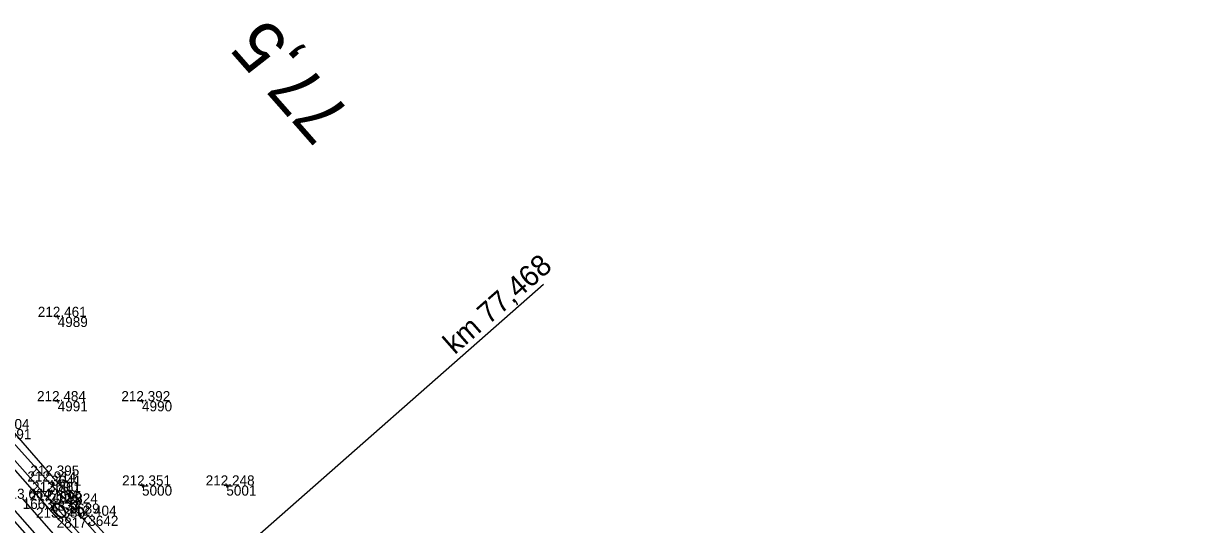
# Model space of a CAD drawing. Extents: x -556590 to -554855, y -1137918 to -1135717.
# Drawn here: x -555624.1 to -555484.8, y -1136484.6 to -1136425.2 of the extents above; entities that cross this region are included whole.
import ezdxf

# ---------------------------------------------------------------- set-up
doc = ezdxf.new("R2010")
doc.units = 0
for name, color, linetype in [('Vrstva 1', 7, 'Continuous'), ('Vrstva 4', 7, 'Continuous'), ('Vrstva 48', 7, 'Continuous'), ('Vrstva 49', 7, 'Continuous'), ('Vrstva 60', 7, 'Continuous'), ('Vrstva 61', 7, 'Continuous'), ('Vrstva 7', 7, 'Continuous'), ('Vrstva 9', 7, 'Continuous')]:
    doc.layers.add(name, color=color, linetype=linetype)

msp = doc.modelspace()

# ---------------------------------------------------------------- linework, layer by layer
at = {"layer": 'Vrstva 1'}
msp.add_lwpolyline([(-555484.83, -1136640), (-555491.53, -1136632.38), (-555498.41, -1136624.55), (-555504.95, -1136617.11), (-555511.61, -1136609.53), (-555518.45, -1136601.75), (-555525.81, -1136593.38), (-555532.45, -1136585.84), (-555538.8, -1136578.61), (-555545.38, -1136571.15), (-555549.37, -1136566.6), (-555556.02, -1136559.04), (-555563.24, -1136550.83), (-555569.21, -1136544.04), (-555575.76, -1136536.6), (-555582.67, -1136528.74), (-555589.18, -1136521.33), (-555595.93, -1136513.66), (-555603.17, -1136505.43), (-555610, -1136497.67), (-555617.05, -1136489.66), (-555624.15, -1136481.58)], dxfattribs=at)
at = {"layer": 'Vrstva 4'}
for points in [[(-555629.91, -1136471.62), (-555620.89, -1136481.78), (-555617.27, -1136485.88)], [(-555633.98, -1136472.93), (-555622.46, -1136485.97), (-555610.79, -1136499.26), (-555598.98, -1136512.7), (-555590.54, -1136522.31), (-555579.05, -1136535.31), (-555569.81, -1136545.79), (-555557.36, -1136559.91), (-555552.62, -1136565.36), (-555551.75, -1136566.43), (-555551.55, -1136566.96), (-555551.52, -1136567.33), (-555551.58, -1136567.56), (-555554.52, -1136564.03), (-555567.11, -1136549.89), (-555580.38, -1136534.94), (-555595.88, -1136517.38), (-555608.09, -1136503.55), (-555622.43, -1136487.28), (-555632.95, -1136475.38)], [(-555527.95, -1136588.27), (-555529.84, -1136586.47), (-555535.2, -1136580.28), (-555544.63, -1136569.62), (-555554.91, -1136557.94), (-555561.61, -1136550.38), (-555568.59, -1136542.49), (-555575.12, -1136534.99), (-555586.39, -1136522.08), (-555596.44, -1136510.59), (-555607.81, -1136497.74), (-555613.59, -1136490.92), (-555614.19, -1136490.14), (-555614.5, -1136489.88), (-555614.86, -1136489.81), (-555615.23, -1136489.54), (-555615.64, -1136488.97), (-555615.94, -1136488.43), (-555617.22, -1136486.81), (-555618.03, -1136485.9), (-555620.12, -1136483.81), (-555629.06, -1136473.63)]]:
    msp.add_lwpolyline(points, dxfattribs=at)
at = {"layer": 'Vrstva 48'}
for p, q in [((-555617.9, -1136482.92), (-555617.4, -1136482.48)), ((-555617.41, -1136483.48), (-555617.15, -1136483.25)), ((-555616.91, -1136484.04), (-555616.38, -1136483.58)), ((-555616.41, -1136484.6), (-555616.15, -1136484.37))]:
    msp.add_line(p, q, dxfattribs=at)
at = {"layer": 'Vrstva 49'}
for p, q in [((-555619.75, -1136459.95), (-555620.25, -1136460.05)), ((-555620.05, -1136459.75), (-555619.95, -1136460.25)), ((-555619.75, -1136469.95), (-555620.25, -1136470.05)), ((-555620.05, -1136469.75), (-555619.95, -1136470.25)), ((-555609.75, -1136469.95), (-555610.25, -1136470.05)), ((-555610.05, -1136469.75), (-555609.95, -1136470.25)), ((-555620.72, -1136480.53), (-555620.63, -1136481.02)), ((-555609.75, -1136479.95), (-555610.25, -1136480.05)), ((-555610.05, -1136479.75), (-555609.95, -1136480.25)), ((-555599.75, -1136479.95), (-555600.25, -1136480.05)), ((-555600.05, -1136479.75), (-555599.95, -1136480.25)), ((-555620.43, -1136480.73), (-555620.92, -1136480.82))]:
    msp.add_line(p, q, dxfattribs=at)
for points in [[(-555628.03, -1136470.49), (-555620.78, -1136478.83), (-555616.37, -1136483.59), (-555611.35, -1136489.14)], [(-555614.37, -1136486.92), (-555618.59, -1136482.14), (-555621.14, -1136479.53), (-555626.69, -1136473.31)]]:
    msp.add_lwpolyline(points, dxfattribs=at)
at = {"layer": 'Vrstva 60'}
for p, q in [((-555620, -1136460), (-555620, -1136460)), ((-555620, -1136470), (-555620, -1136470)), ((-555610, -1136470), (-555610, -1136470)), ((-555620.78, -1136478.83), (-555620.78, -1136478.83)), ((-555621.14, -1136479.53), (-555621.14, -1136479.53)), ((-555610, -1136480), (-555610, -1136480)), ((-555600, -1136480), (-555600, -1136480)), ((-555620.89, -1136481.78), (-555620.89, -1136481.78)), ((-555620.68, -1136480.77), (-555620.68, -1136480.77)), ((-555618.59, -1136482.14), (-555618.59, -1136482.14)), ((-555620.12, -1136483.81), (-555620.12, -1136483.81)), ((-555616.37, -1136483.59), (-555616.37, -1136483.59))]:
    msp.add_line(p, q, dxfattribs=at)
at = {"layer": 'Vrstva 9'}
msp.add_line((-555607.49, -1136495.79), (-555562.37, -1136456.1), dxfattribs=at)

# ---------------------------------------------------------------- texts
at = {"layer": 'Vrstva 48'}
msp.add_text('0,4', height=2, rotation=41.3888, dxfattribs=at).set_placement((-555619.72, -1136484.2))
at = {"layer": 'Vrstva 60'}
for s, p in [('4989', (-555620, -1136461.2)), ('4991', (-555620, -1136471.2)), ('4990', (-555610, -1136471.2)), ('3691', (-555626.69, -1136474.51)), ('3641', (-555620.78, -1136480.03)), ('3690', (-555621.14, -1136480.73)), ('5000', (-555610, -1136481.2)), ('5001', (-555600, -1136481.2)), ('1663', (-555624.15, -1136482.78)), ('2831', (-555620.89, -1136482.98)), ('4999', (-555620.68, -1136481.97)), ('3689', (-555618.59, -1136483.34)), ('2817', (-555620.12, -1136485.01)), ('3642', (-555616.37, -1136484.79))]:
    msp.add_text(s, height=1.2, dxfattribs=at).set_placement(p)
at = {"layer": 'Vrstva 61'}
for s, p in [('212.461', (-555622.36, -1136460)), ('212.484', (-555622.45, -1136470)), ('212.392', (-555612.45, -1136470)), ('213.004', (-555629.14, -1136473.31)), ('212.395', (-555623.24, -1136478.83)), ('212.914', (-555623.59, -1136479.53)), ('212.351', (-555612.36, -1136480)), ('212.248', (-555602.45, -1136480)), ('213.664', (-555626.6, -1136481.58)), ('212.854', (-555623.34, -1136481.78)), ('212.861', (-555623.04, -1136480.77)), ('212.824', (-555621.04, -1136482.14)), ('213.380', (-555622.57, -1136483.81)), ('212.404', (-555618.82, -1136483.59))]:
    msp.add_text(s, height=1.2, dxfattribs=at).set_placement(p)
at = {"layer": 'Vrstva 7'}
msp.add_text('77,5', height=6, rotation=131.3137, dxfattribs=at).set_placement((-555585, -1136436))
at = {"layer": 'Vrstva 9'}
msp.add_text('km 77,468', height=2.5, rotation=41.3388, dxfattribs=at).set_placement((-555572.92, -1136464.54))

doc.saveas('drawing.dxf')
